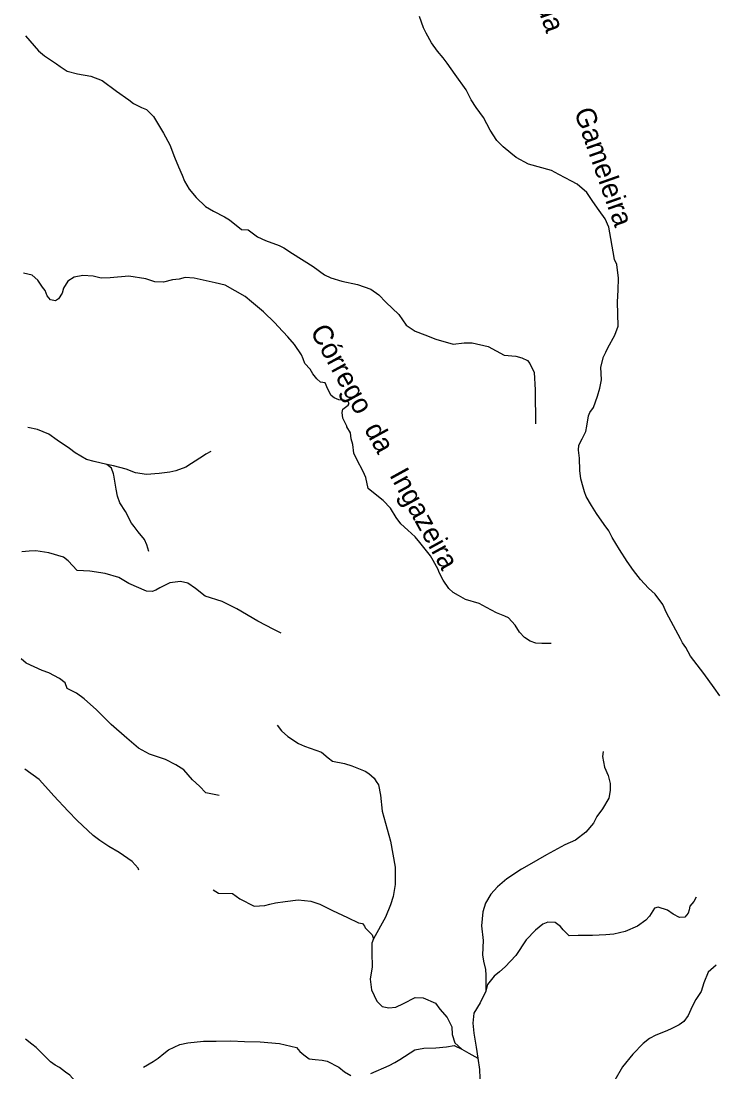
# Model space of a CAD drawing. Extents: x 717.8 to 772.7, y 8672.2 to 8728.
# Drawn here: x 718.07 to 725.02, y 8710.22 to 8720.68 of the extents above; entities that cross this region are included whole.
import ezdxf
from ezdxf.enums import TextEntityAlignment as Align

# ---------------------------------------------------------------- set-up
doc = ezdxf.new("R2010")
doc.units = 0
doc.header["$LTSCALE"] = 0.08
doc.linetypes.add('LONG_DASHED', pattern=[7.5, 6, -1.5])
doc.layers.add('61', color=7, linetype='Continuous')
doc.layers.add('9', color=7, linetype='LONG_DASHED', lineweight=25)

msp = doc.modelspace()

# ---------------------------------------------------------------- linework, layer by layer
at = {"layer": '9'}
for points in [[(725.0205, 8713.9663), (724.964, 8714.0443), (724.8604, 8714.1878), (724.7276, 8714.3597), (724.6816, 8714.4459), (724.6481, 8714.492), (724.6274, 8714.533), (724.4895, 8714.7918), (724.4506, 8714.8737), (724.3769, 8714.9782), (724.31, 8715.0384), (724.2297, 8715.1239), (724.1599, 8715.2124), (724.0984, 8715.3028), (724.0199, 8715.4224), (723.949, 8715.5428), (723.9152, 8715.6088), (723.8667, 8715.6705), (723.7908, 8715.7793), (723.7424, 8715.8603), (723.6905, 8715.9485), (723.6725, 8715.9971), (723.6598, 8716.0415), (723.6354, 8716.1272), (723.6265, 8716.2075), (723.6234, 8716.3302), (723.613, 8716.4098), (723.6153, 8716.4611), (723.6495, 8716.5252), (723.6867, 8716.5981), (723.6943, 8716.6492), (723.7116, 8716.7529), (723.7246, 8716.7874), (723.7634, 8716.8349), (723.8023, 8716.9472), (723.8239, 8717.0292), (723.8418, 8717.1112), (723.8349, 8717.237), (723.8628, 8717.3399), (723.8845, 8717.3875), (723.9061, 8717.4307), (723.974, 8717.5576), (724.006, 8717.6457), (724.0018, 8717.8875), (724.0081, 8718.0034), (724.0104, 8718.125), (723.9929, 8718.2594), (723.9706, 8718.3083), (723.9355, 8718.5199), (723.9153, 8718.6323), (723.879, 8718.7142), (723.8201, 8718.7976), (723.7553, 8718.8883), (723.6973, 8718.9749), (723.5996, 8719.0588), (723.5435, 8719.0903), (723.4183, 8719.1551), (723.3452, 8719.1942), (723.1166, 8719.2579), (722.9917, 8719.3248), (722.9392, 8719.3681), (722.8647, 8719.4305), (722.8015, 8719.4937), (722.7334, 8719.5966), (722.6673, 8719.7236), (722.5943, 8719.8222), (722.5446, 8719.9003), (722.4966, 8719.998), (722.3871, 8720.1522), (722.3062, 8720.2637), (722.2674, 8720.3158), (722.2104, 8720.3829), (722.1507, 8720.4669), (722.0961, 8720.564), (722.0712, 8720.6158), (722.0322, 8720.7301)], [(718.1091, 8720.537), (718.2409, 8720.3873), (718.2989, 8720.3362), (718.4194, 8720.2563), (718.455, 8720.2297), (718.5258, 8720.1855), (718.6272, 8720.1569), (718.7607, 8720.1343), (718.8731, 8720.0926), (719.0162, 8719.9836), (719.139, 8719.8978), (719.1837, 8719.8632), (719.2635, 8719.8235), (719.3142, 8719.8033), (719.3839, 8719.7326), (719.4837, 8719.5674), (719.5461, 8719.4509), (719.5938, 8719.3279), (719.6314, 8719.233), (719.6698, 8719.1481), (719.6914, 8719.0879), (719.7383, 8719.008), (719.81, 8718.9271), (719.9029, 8718.8373), (719.9808, 8718.7906), (720.0917, 8718.7344), (720.1404, 8718.7032), (720.2599, 8718.6079), (720.3272, 8718.6043), (720.4185, 8718.5365), (720.4989, 8718.4981), (720.6333, 8718.4502), (720.6824, 8718.4251), (720.7682, 8718.3684), (720.9725, 8718.2394), (721.0859, 8718.1561), (721.1474, 8718.1275), (721.2566, 8718.0924), (721.4152, 8718.0608), (721.5462, 8718.0145), (721.626, 8717.9578), (721.6968, 8717.884), (721.8248, 8717.762), (721.8986, 8717.6561), (721.9884, 8717.5948), (722.0842, 8717.5577), (722.1931, 8717.5166), (722.3654, 8717.4666), (722.4738, 8717.4805), (722.5536, 8717.481), (722.7157, 8717.4438), (722.8738, 8717.3579), (722.9898, 8717.3485), (723.0486, 8717.3319), (723.1058, 8717.3038), (723.1289, 8717.2742), (723.172, 8717.1838), (723.182, 8717.0122), (723.1825, 8716.8676)], [(723.3413, 8714.4862), (723.2485, 8714.4875), (723.1898, 8714.4906), (723.1314, 8714.5108), (723.077, 8714.5467), (723.0275, 8714.6005), (722.9818, 8714.6698), (722.9156, 8714.7428), (722.8798, 8714.7582), (722.7957, 8714.7904), (722.6962, 8714.846), (722.6232, 8714.8862), (722.4872, 8714.9258), (722.4205, 8714.9629), (722.3667, 8714.9926), (722.3218, 8715.0341), (722.265, 8715.1176), (722.226, 8715.1918), (722.2166, 8715.2228), (722.1683, 8715.3131), (722.1399, 8715.3582), (722.0348, 8715.4912), (721.9887, 8715.5498), (721.9163, 8715.6135), (721.8449, 8715.6767), (721.7992, 8715.7423), (721.7423, 8715.8338), (721.6693, 8715.9098), (721.589, 8715.9715), (721.52, 8716.0297), (721.4959, 8716.1391), (721.4693, 8716.1973), (721.4058, 8716.317), (721.3778, 8716.3815), (721.3661, 8716.4675), (721.3525, 8716.5237), (721.3438, 8716.585), (721.3086, 8716.6423), (721.307, 8716.6487), (721.2696, 8716.7307), (721.2622, 8716.7864), (721.2687, 8716.819), (721.3221, 8716.8598), (721.3319, 8716.8767), (721.3165, 8716.8977), (721.2788, 8716.9098), (721.2288, 8716.9113), (721.1831, 8716.9305), (721.1508, 8716.9559), (721.1183, 8717.0187), (721.0927, 8717.0802), (721.0451, 8717.0894), (721.0107, 8717.1215), (720.9703, 8717.1702), (720.9431, 8717.2187), (720.8912, 8717.275), (720.8745, 8717.3207), (720.8554, 8717.3617), (720.7885, 8717.4637), (720.7224, 8717.5404), (720.6259, 8717.6424), (720.5907, 8717.6777), (720.479, 8717.7888), (720.3589, 8717.8878), (720.2954, 8717.9393), (720.1965, 8717.9968), (720.0973, 8718.0525), (719.9984, 8718.0754), (719.7894, 8718.1218), (719.6992, 8718.1317), (719.6398, 8718.115), (719.5718, 8718.1057), (719.4852, 8718.0852), (719.398, 8718.0883), (719.3096, 8718.118), (719.139, 8718.1434), (718.9529, 8718.1266), (718.8626, 8718.1241), (718.7852, 8718.144), (718.6796, 8718.1501), (718.5937, 8718.1346), (718.5306, 8718.095), (718.4892, 8718.0226), (718.4756, 8717.9756), (718.4398, 8717.9175), (718.4107, 8717.8977), (718.3582, 8717.9088), (718.3273, 8717.9465), (718.305, 8718.0022), (718.2797, 8718.0344), (718.2333, 8718.1049), (718.1783, 8718.1521), (718.0923, 8718.1735)], [(723.1825, 8716.8676), (723.1864, 8716.8047), (723.1849, 8716.6747)], [(718.9214, 8716.2697), (718.7937, 8716.2988), (718.7189, 8716.3196), (718.6032, 8716.3845), (718.549, 8716.428), (718.4269, 8716.5109), (718.3432, 8716.5692), (718.2313, 8716.6165), (718.1355, 8716.6353)], [(719.9555, 8716.3967), (719.9066, 8716.3713), (719.8813, 8716.3532), (719.7623, 8716.2775), (719.7045, 8716.2415), (719.6069, 8716.2055), (719.547, 8716.1919), (719.441, 8716.1773), (719.3143, 8716.1689), (719.2041, 8716.1845), (719.1127, 8716.2209), (718.9859, 8716.2537), (718.9214, 8716.2697)], [(719.3377, 8715.4032), (719.3174, 8715.4684), (719.2944, 8715.5221), (719.2331, 8715.5973), (719.1922, 8715.6519), (719.1669, 8715.6844), (719.1055, 8715.8), (719.0478, 8715.8868), (719.0261, 8715.9518), (719.0117, 8716.024), (718.9901, 8716.1613), (718.9864, 8716.1757), (718.9647, 8716.2335), (718.9214, 8716.2697)], [(720.6557, 8714.5888), (720.5821, 8714.6255), (720.4207, 8714.7075), (720.2123, 8714.8307), (720.067, 8714.9058), (719.8991, 8714.9579), (719.8013, 8715.0325), (719.7267, 8715.0856), (719.6517, 8715.104), (719.5454, 8715.0896), (719.448, 8715.0414), (719.4077, 8715.0176), (719.3695, 8715.0056), (719.3158, 8715.0081), (719.1404, 8715.0837), (719.0395, 8715.1418), (718.9029, 8715.1816), (718.7502, 8715.2073), (718.6247, 8715.2124), (718.5353, 8715.3093), (718.4871, 8715.3471), (718.343, 8715.3903), (718.2127, 8715.4083), (718.1487, 8715.4068), (718.0744, 8715.3973)], [(720.036, 8712.9733), (719.9048, 8712.9984), (719.8424, 8713.0673), (719.7737, 8713.1298), (719.6864, 8713.2299), (719.6052, 8713.28), (719.5052, 8713.3301), (719.344, 8713.3862), (719.2347, 8713.4435), (719.118, 8713.543), (718.962, 8713.6806), (718.8182, 8713.8244), (718.6934, 8713.937), (718.6185, 8713.9934), (718.5248, 8714.0372), (718.506, 8714.0934), (718.4498, 8714.1372), (718.3436, 8714.1936), (718.2749, 8714.2187), (718.1182, 8714.2898), (718.0662, 8714.333)], [(720.6132, 8713.6748), (720.6571, 8713.6184), (720.7197, 8713.562), (720.8257, 8713.4916), (720.8862, 8713.463), (721.0542, 8713.4032), (721.1237, 8713.3491), (721.1669, 8713.3136), (721.283, 8713.2913), (721.358, 8713.2672), (721.4916, 8713.2159), (721.5282, 8713.1923), (721.5801, 8713.145), (721.601, 8713.1141), (721.6246, 8713.0805), (721.6444, 8712.9762), (721.6603, 8712.817), (721.742, 8712.5191), (721.7877, 8712.2587), (721.7899, 8712.0881), (721.7685, 8711.9677), (721.7431, 8711.8831), (721.6913, 8711.7626), (721.5725, 8711.5447)], [(723.8583, 8713.4116), (723.8511, 8713.3622), (723.8723, 8713.2564), (723.9076, 8713.1717), (723.9287, 8713.0941), (723.9286, 8713.0235), (723.9145, 8712.946), (723.8509, 8712.8401), (723.7962, 8712.7634), (723.7632, 8712.6992), (723.6844, 8712.6075), (723.5825, 8712.5294), (723.4754, 8712.4828), (723.293, 8712.381), (723.1235, 8712.282), (723.0459, 8712.2396), (722.8996, 8712.1421), (722.8077, 8712.0643), (722.7421, 8711.9922), (722.6892, 8711.8998), (722.6617, 8711.8136), (722.6471, 8711.676), (722.6655, 8711.5312), (722.6563, 8711.3882), (722.6691, 8711.324), (722.689, 8711.2425), (722.6898, 8711.1835), (722.69, 8711.0254)], [(719.2388, 8712.2284), (719.2304, 8712.2506), (719.1711, 8712.3152), (719.0442, 8712.4041), (718.9405, 8712.4655), (718.8506, 8712.5237), (718.785, 8712.5744), (718.6242, 8712.7258), (718.5343, 8712.8157), (718.3914, 8712.9692), (718.3407, 8713.0295), (718.2454, 8713.1311), (718.1037, 8713.2369)], [(719.9783, 8712.0352), (720.0308, 8712.0004), (720.1705, 8711.9962), (720.2432, 8711.9429), (720.3854, 8711.8726), (720.4913, 8711.8793), (720.5401, 8711.8923), (720.5996, 8711.903), (720.6952, 8711.9174), (720.8222, 8711.9352), (720.9507, 8711.9208), (721.0379, 8711.8929), (721.1657, 8711.8277), (721.3138, 8711.7591), (721.423, 8711.7058), (721.4636, 8711.6982), (721.4839, 8711.6718), (721.4899, 8711.6541), (721.561, 8711.5873), (721.5725, 8711.5447)], [(724.783, 8711.9606), (724.7618, 8711.9183), (724.7223, 8711.8708), (724.7134, 8711.8334), (724.7033, 8711.8001), (724.6695, 8711.7621), (724.619, 8711.7574), (724.5561, 8711.7918), (724.4979, 8711.8328), (724.4057, 8711.8607), (724.3695, 8711.8512), (724.3203, 8711.7728), (724.2835, 8711.7318), (724.1986, 8711.6707), (724.0757, 8711.6184), (723.963, 8711.5914), (723.886, 8711.5866), (723.7519, 8711.5794), (723.6107, 8711.5794), (723.5185, 8711.5763), (723.4616, 8711.6374), (723.4325, 8711.6701), (723.3791, 8711.7093), (723.3078, 8711.7116), (723.2576, 8711.6923), (723.185, 8711.6315), (723.0924, 8711.5347), (722.9892, 8711.3811), (722.8832, 8711.268), (722.8268, 8711.2184), (722.7735, 8711.174), (722.7082, 8711.0921), (722.69, 8711.0254)], [(721.5725, 8711.5447), (721.5553, 8711.5045), (721.5574, 8711.4058), (721.5583, 8711.2663), (721.5402, 8711.1447), (721.5529, 8711.0383), (721.5794, 8710.9825), (721.6072, 8710.9267), (721.6595, 8710.8731), (721.7268, 8710.8576), (721.7954, 8710.8672), (721.8702, 8710.9039), (721.9885, 8710.9614), (722.0685, 8710.9587), (722.1885, 8710.905), (722.2335, 8710.8455), (722.3062, 8710.7635), (722.3531, 8710.6703), (722.3571, 8710.5921), (722.3812, 8710.5103), (722.452, 8710.4474)], [(724.9822, 8711.2856), (724.9043, 8711.2152), (724.8613, 8711.1097), (724.8343, 8711.0229), (724.7789, 8710.9426), (724.7436, 8710.8721), (724.7041, 8710.7829), (724.6619, 8710.724), (724.6151, 8710.6906), (724.5299, 8710.6481), (724.4764, 8710.6242), (724.3838, 8710.5885), (724.3189, 8710.5523), (724.2574, 8710.5033), (724.155, 8710.3993), (724.0515, 8710.2727), (723.9741, 8710.1391)], [(722.69, 8711.0254), (722.6329, 8710.9089), (722.5709, 8710.8063), (722.5608, 8710.7071), (722.5727, 8710.6068), (722.5953, 8710.4678), (722.6115, 8710.3574)], [(718.9257, 8709.7786), (718.9041, 8709.8397), (718.8824, 8709.8779), (718.8346, 8709.9324), (718.7314, 8709.9847), (718.6569, 8710.0565), (718.6098, 8710.1273), (718.5531, 8710.1891), (718.5103, 8710.2199), (718.4485, 8710.2639), (718.4065, 8710.2893), (718.3588, 8710.3206), (718.2155, 8710.4639), (718.1735, 8710.4989), (718.1092, 8710.5486)], [(719.2844, 8710.2675), (719.3808, 8710.3259), (719.4302, 8710.3591), (719.4876, 8710.4039), (719.532, 8710.4425), (719.6456, 8710.4952), (719.7268, 8710.5106), (719.8833, 8710.529), (720.0071, 8710.5262), (720.1534, 8710.5292), (720.2911, 8710.5247), (720.4455, 8710.5207), (720.6381, 8710.5053), (720.8064, 8710.464), (720.84, 8710.4232), (720.8793, 8710.3916), (720.9315, 8710.3517), (720.9912, 8710.345), (721.0634, 8710.3392), (721.1137, 8710.3292), (721.2276, 8710.2682), (721.2841, 8710.2232), (721.3483, 8710.1869)], [(721.5462, 8710.2053), (721.7284, 8710.2842), (721.784, 8710.3161), (721.8365, 8710.3443), (721.9849, 8710.4398), (722.074, 8710.4571), (722.1949, 8710.4617), (722.3003, 8710.4726), (722.3752, 8710.4844), (722.452, 8710.4474)], [(722.452, 8710.4474), (722.5228, 8710.408), (722.6115, 8710.3574)], [(722.6115, 8710.3574), (722.6274, 8710.2456), (722.6327, 8710.1594), (722.6236, 8710.1025), (722.6029, 8710.0458), (722.5616, 8709.9557), (722.5404, 8709.9074), (722.4842, 8709.8128), (722.4428, 8709.5937), (722.4447, 8709.5496), (722.4634, 8709.4397), (722.4673, 8709.3828), (722.4438, 8709.3327), (722.4114, 8709.269), (722.3712, 8709.1885), (722.3173, 8709.0904), (722.2712, 8709.007), (722.2506, 8708.955), (722.2364, 8708.825), (722.2152, 8708.726), (722.1895, 8708.6858), (722.187, 8708.6624)]]:
    msp.add_lwpolyline(points, dxfattribs=at)

# ---------------------------------------------------------------- texts
at = {"layer": '61'}
for s, rotation, p in [('Córrego            da           Gameleira', 289.422, (723.2773, 8720.6026)), ('Córrego  da   Ingazeira', 298.826, (721.5979, 8716.399))]:
    msp.add_text(s, height=0.2, rotation=rotation, dxfattribs=at).set_placement(p, align=Align.CENTER)

doc.saveas('drawing.dxf')
